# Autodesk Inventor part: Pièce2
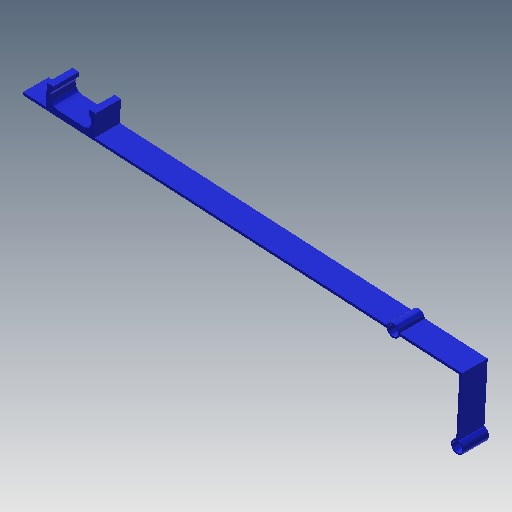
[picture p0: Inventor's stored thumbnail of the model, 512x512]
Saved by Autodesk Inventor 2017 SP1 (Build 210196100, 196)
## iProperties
Created: 2013-05
Part Number: Pièce2
Material: Générique
Document SubType Name: Modeling
Designer: jost thierry
Density: 1 g/cm^3
Mass: 2.58776 g
Surface Area: 51.6813 cm^2
Volume: 2.58776 cm^3
Appearance: Bleu - Peinture murale - Brillant
Author: jost thierry
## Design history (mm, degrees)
sketch "Esquisse1"
  geometry: L1 (-10.466, -2.433)-(-0.164, -2.996); L2 (4.171, -3.232)-(4.553, 3.757); L3 (4.553, 3.757)-(2.056, 3.894); L4 (2.056, 3.894)-(1.968, 2.265); L5 (-14.801, -2.196)-(-14.419, 4.793); L6 (-14.419, 4.793)-(-11.923, 4.657); L7 (-11.923, 4.657)-(-12.012, 3.028); L8 (-14.801, -2.196)-(-14.878, -3.612); L9 (-14.878, -3.612)-(4.171, -4.652); L10 (4.171, -4.652)-(4.189, -2.904); A1 r 3 centre (0, 0) between (-0.164, -2.996) and (1.968, 2.265); A2 r 3 centre (-10.302, 0.562) between (-12.012, 3.028) and (-10.466, -2.433); 2 further points
  constraints: 20 end point, 4 point on circle, 3 perpendicular, 2 centre point, 2 coincident, 2 parallel, 1 point on line, 1 tangent
  dimensions: "d0" = 6 diameter of A1; "d1" = 2.5 distance between parallel lines of L4 L2; "d2" = 7 distance between parallel lines of L1 L3; "d3" = 19 distance of L2.start L5.start
extrude "Extrusion1" new body sketch "Esquisse1" stored distance "d4" = 10; taper "d5" = 0 deg
sketch "Esquisse2"
  geometry: L1 (19.077, 10)-(0, 10) reference; L2 (19.077, 10)-(19.077, 0) reference; L3 (-8.923, 10)-(163.077, 10); L4 (163.077, 10)-(163.077, 0); L5 (163.077, 0)-(-8.923, 0); L6 (-8.923, 0)-(-8.923, 10); 2 further points
  constraints: 8 end point, 2 horizontal, 2 parallel, 1 collinear, 1 perpendicular, 1 other
  dimensions: "d6" = 28 distance between parallel lines of L2 L6; "d7" = 172 distance between parallel lines of L4 L6
extrude "Extrusion2" join sketch "Esquisse2" distance "d8" = 1; taper "d9" = 0 deg
sketch "Esquisse3"
  geometry: L1 (0, -1)-(10, -1) reference; L2 (10, 0)-(10, -1) reference; L3 (0, 0)-(10, 0) reference; L4 (0, 0)-(0, -1) reference; L5 (0, 0)-(10, 0); L6 (10, 0)-(10, -26); L7 (10, -26)-(0, -26); L8 (0, -26)-(0, 0); 1 further point
  constraints: 8 end point, 2 parallel, 1 collinear, 1 horizontal, 1 perpendicular, 1 point on line
  dimensions: "d10" = 10 distance of L5.start L5.end; "d11" = 26 distance of L7.end L5.start
extrude "Extrusion3" join sketch "Esquisse3" distance "d12" = 1; taper "d13" = 0 deg
sketch "Esquisse4"
  geometry: L1 (146.54, -38.464)-(145.541, -38.41) reference; C1 r 2.5 at (146.04, -38.437)
  constraints: 1 centre point, 1 midpoint
  dimensions: "d14" = 5 diameter of C1
extrude "Extrusion4" join sketch "Esquisse4" distance "d15" = 10; taper "d16" = 0 deg
sketch "Esquisse5"
  geometry: C1 r 2 at (146.04, -38.437); A1 r 2.5 centre (146.04, -38.437) between (145.675, -35.964) and (146.673, -36.018) reference
  constraints: 1 centre point, 1 coincident
  dimensions: "d17" = 4 diameter of C1
extrude "Extrusion5" cut sketch "Esquisse5" stored distance "d18" = 10; taper "d19" = 0 deg
sketch "Esquisse6"
  geometry: C1 r 2.5 at (120.975, -11.53)
  constraints: 1 centre point
  dimensions: "d20" = 5 diameter of C1
extrude "Extrusion6" join sketch "Esquisse6" distance "d22" = 10; taper "d23" = 0 deg
sketch "Esquisse7"
  geometry: C1 r 2 at (120.975, -11.53); A1 r 2.5 centre (120.975, -11.53) between (118.501, -11.896) and (123.393, -12.163) reference
  constraints: 1 centre point, 1 coincident
  dimensions: "d24" = 4 diameter of C1
extrude "Extrusion7" cut sketch "Esquisse7" distance "d25" = 10; taper "d26" = 0 deg
node "Solide1"
